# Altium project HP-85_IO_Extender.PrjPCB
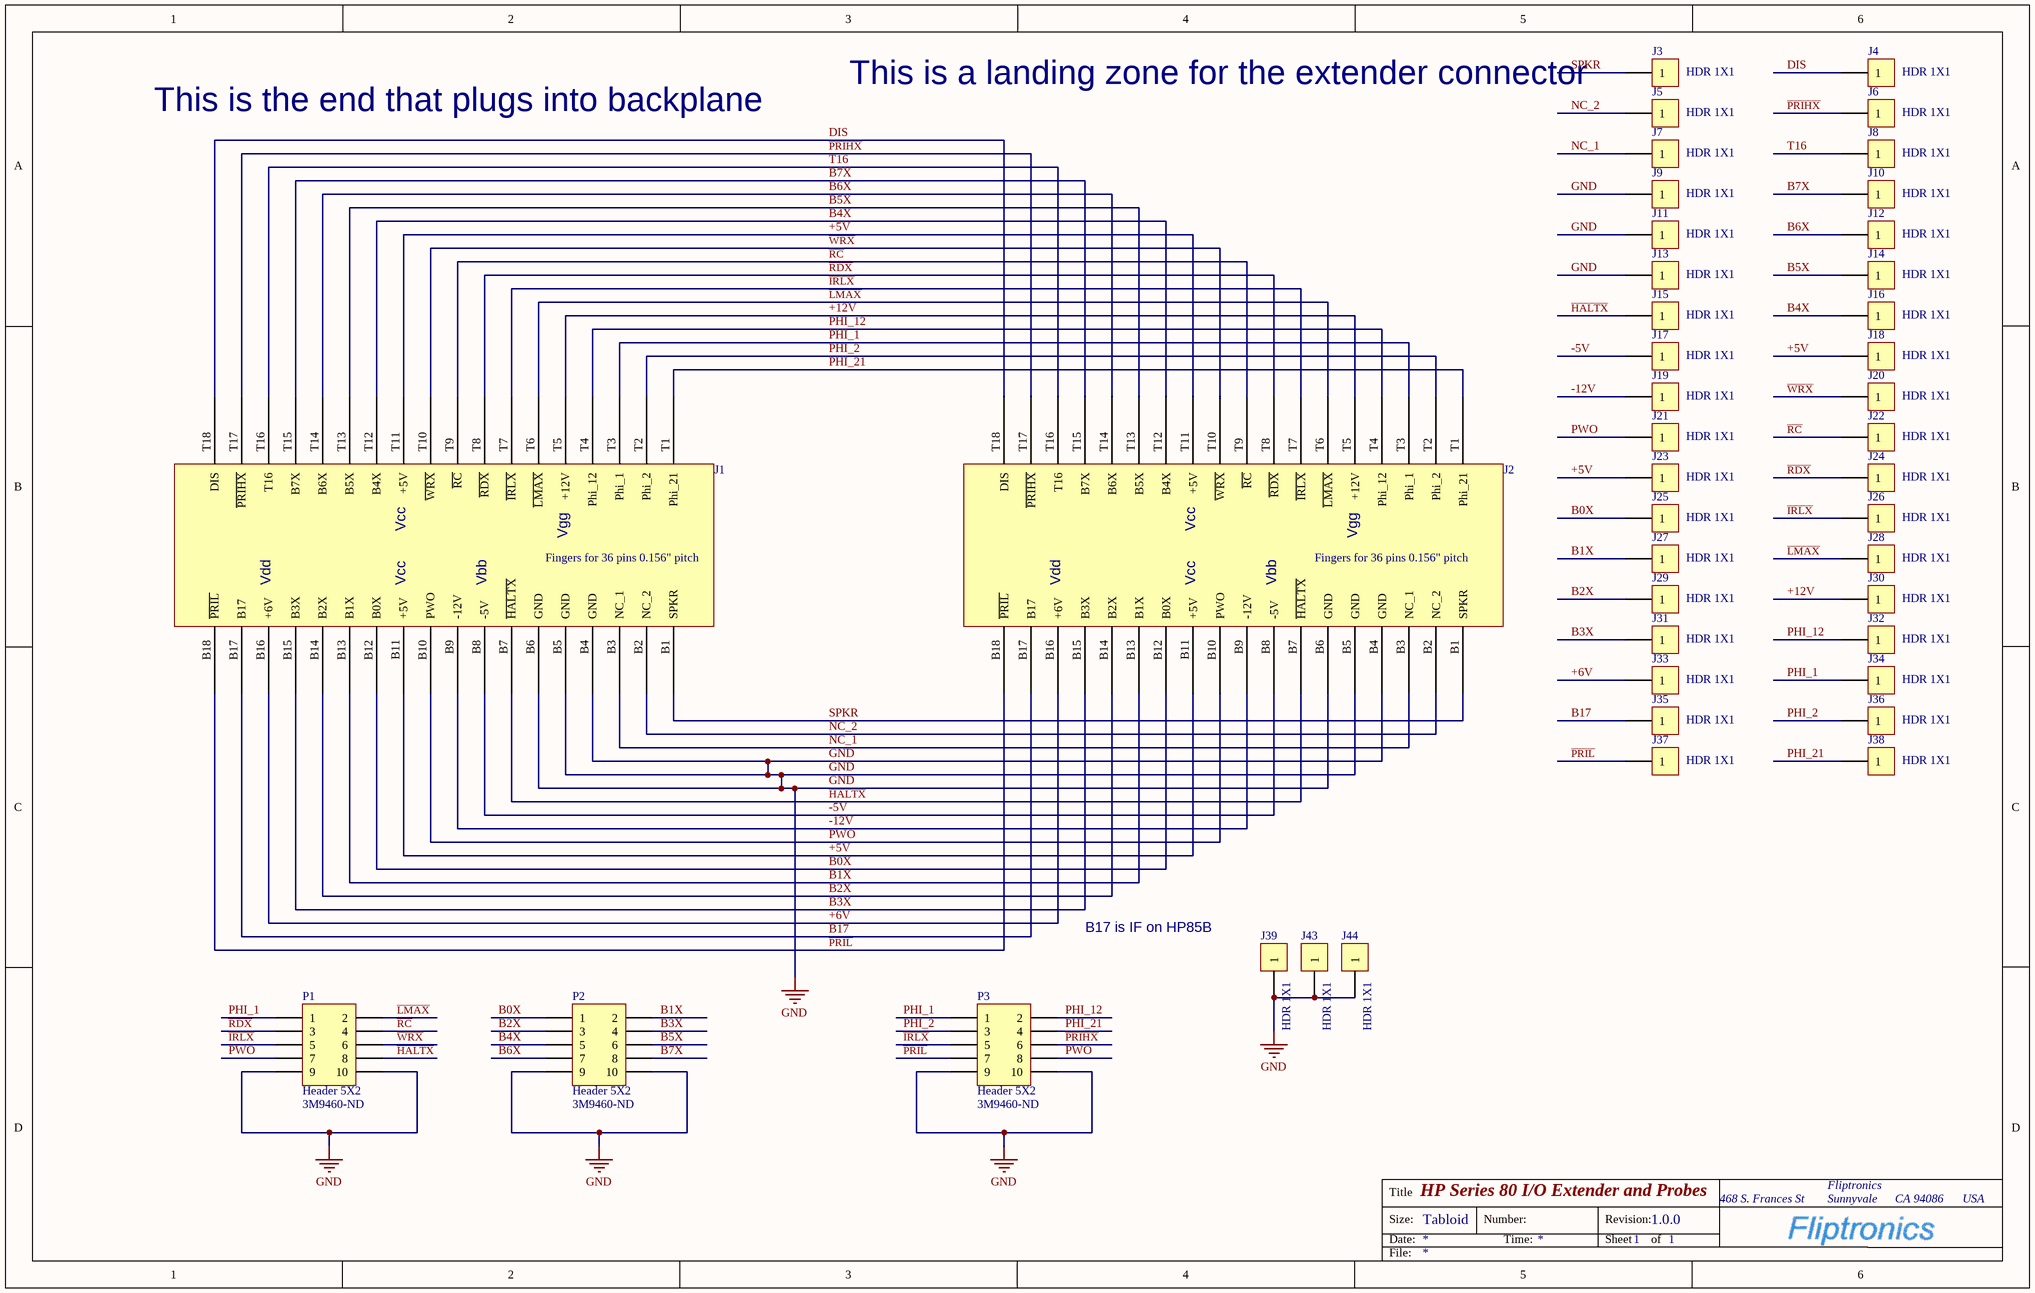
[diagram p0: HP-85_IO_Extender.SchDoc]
1 sheet, 44 parts. Net scope: global (net labels, ports and power ports of the same name join across sheets).
Board file: HP-85_IO_Extender.PcbDoc

## Sheet HP-85_IO_Extender.SchDoc: HP Series 80 I/O Extender and Probes
size B; ApprovedBy: Philip Freidin; CheckedBy: Philip Freidin; Author: Philip Freidin; Organization: Fliptronics; Address1: 468 S. Frances St; Address2: Sunnyvale; Address3: CA 94086; Address4: USA; Revision: 1.0.0; SheetNumber: 1; SheetTotal: 1

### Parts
J1  Fingers for 36 pins 0.156" pitch  [Fingers for 36 pins 0.156" pitch]
J2  Fingers for 36 pins 0.156" pitch  [Fingers for 36 pins 0.156" pitch]
J3  HDR 1X1  [HDR_1X1_2MM54_round]
J4  HDR 1X1  [HDR_1X1_2MM54_round]
J5  HDR 1X1  [HDR_1X1_2MM54_round]
J6  HDR 1X1  [HDR_1X1_2MM54_round]
J7  HDR 1X1  [HDR_1X1_2MM54_round]
J8  HDR 1X1  [HDR_1X1_2MM54_round]
J9  HDR 1X1  [HDR_1X1_2MM54_round]
J10  HDR 1X1  [HDR_1X1_2MM54_round]
J11  HDR 1X1  [HDR_1X1_2MM54_round]
J12  HDR 1X1  [HDR_1X1_2MM54_round]
J13  HDR 1X1  [HDR_1X1_2MM54_round]
J14  HDR 1X1  [HDR_1X1_2MM54_round]
J15  HDR 1X1  [HDR_1X1_2MM54_round]
J16  HDR 1X1  [HDR_1X1_2MM54_round]
J17  HDR 1X1  [HDR_1X1_2MM54_round]
J18  HDR 1X1  [HDR_1X1_2MM54_round]
J19  HDR 1X1  [HDR_1X1_2MM54_round]
J20  HDR 1X1  [HDR_1X1_2MM54_round]
J21  HDR 1X1  [HDR_1X1_2MM54_round]
J22  HDR 1X1  [HDR_1X1_2MM54_round]
J23  HDR 1X1  [HDR_1X1_2MM54_round]
J24  HDR 1X1  [HDR_1X1_2MM54_round]
J25  HDR 1X1  [HDR_1X1_2MM54_round]
J26  HDR 1X1  [HDR_1X1_2MM54_round]
J27  HDR 1X1  [HDR_1X1_2MM54_round]
J28  HDR 1X1  [HDR_1X1_2MM54_round]
J29  HDR 1X1  [HDR_1X1_2MM54_round]
J30  HDR 1X1  [HDR_1X1_2MM54_round]
J31  HDR 1X1  [HDR_1X1_2MM54_round]
J32  HDR 1X1  [HDR_1X1_2MM54_round]
J33  HDR 1X1  [HDR_1X1_2MM54_round]
J34  HDR 1X1  [HDR_1X1_2MM54_round]
J35  HDR 1X1  [HDR_1X1_2MM54_round]
J36  HDR 1X1  [HDR_1X1_2MM54_round]
J37  HDR 1X1  [HDR_1X1_2MM54_round]
J38  HDR 1X1  [HDR_1X1_2MM54_round]
J39  HDR 1X1  [HDR_1X1_2MM54_round]
J43  HDR 1X1  [HDR_1X1_2MM54_round]
J44  HDR 1X1  [HDR_1X1_2MM54_round]
P1  Header 5X2  Supplier Part Number 1: 3M9460-ND  [HDR_5X2 alt 1]
P2  Header 5X2  Supplier Part Number 1: 3M9460-ND  [HDR_5X2 alt 1]
P3  Header 5X2  Supplier Part Number 1: 3M9460-ND  [HDR_5X2 alt 1]

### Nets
GND: J1.B4(GND) J1.B5(GND) J1.B6(GND) J2.B4(GND) J2.B5(GND) J2.B6(GND) J9.1 J11.1 J13.1 J39.1 J43.1 J44.1 P1.9 P1.10 P2.9 P2.10 P3.9 P3.10
+5V: J1.B11(+5V) J1.T11(+5V) J2.B11(+5V) J2.T11(+5V) J18.1 J23.1
+6V: J1.B16(+6V) J2.B16(+6V) J33.1
+12V: J1.T5(+12V) J2.T5(+12V) J30.1
-5V: J1.B8(-5V) J2.B8(-5V) J17.1
-12V: J1.B9(-12V) J2.B9(-12V) J19.1
~{HALTX}: J1.B7(~{HALTX}) J2.B7(~{HALTX}) J15.1 P1.8
~{IRLX}: J1.T7(~{IRLX}) J2.T7(~{IRLX}) J26.1 P1.5 P3.5
~{LMAX}: J1.T6(~{LMAX}) J2.T6(~{LMAX}) J28.1 P1.2
~{PRIHX}: J1.T17(~{PRIHX}) J2.T17(~{PRIHX}) J6.1 P3.6
~{PRIL}: J1.B18(~{PRIL}) J2.B18(~{PRIL}) J37.1 P3.7
~{RC}: J1.T9(~{RC}) J2.T9(~{RC}) J22.1 P1.4
~{RDX}: J1.T8(~{RDX}) J2.T8(~{RDX}) J24.1 P1.3
~{WRX}: J1.T10(~{WRX}) J2.T10(~{WRX}) J20.1 P1.6
B0X: J1.B12(B0X) J2.B12(B0X) J25.1 P2.1
B1X: J1.B13(B1X) J2.B13(B1X) J27.1 P2.2
B2X: J1.B14(B2X) J2.B14(B2X) J29.1 P2.3
B3X: J1.B15(B3X) J2.B15(B3X) J31.1 P2.4
B4X: J1.T12(B4X) J2.T12(B4X) J16.1 P2.5
B5X: J1.T13(B5X) J2.T13(B5X) J14.1 P2.6
B6X: J1.T14(B6X) J2.T14(B6X) J12.1 P2.7
B7X: J1.T15(B7X) J2.T15(B7X) J10.1 P2.8
B17: J1.B17 J2.B17 J35.1
DIS: J1.T18(DIS) J2.T18(DIS) J4.1
NC_1: J1.B3(NC_1) J2.B3(NC_1) J7.1
NC_2: J1.B2(NC_2) J2.B2(NC_2) J5.1
PHI_1: J1.T3(Phi_1) J2.T3(Phi_1) J34.1 P1.1 P3.1
PHI_2: J1.T2(Phi_2) J2.T2(Phi_2) J36.1 P3.3
PHI_12: J1.T4(Phi_12) J2.T4(Phi_12) J32.1 P3.2
PHI_21: J1.T1(Phi_21) J2.T1(Phi_21) J38.1 P3.4
PWO: J1.B10(PWO) J2.B10(PWO) J21.1 P1.7 P3.8
SPKR: J1.B1(SPKR) J2.B1(SPKR) J3.1
T16: J1.T16 J2.T16 J8.1

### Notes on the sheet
- (near J3) This is a landing zone for the extender connector
- This is the end that plugs into backplane
- B17 is IF on HP85B

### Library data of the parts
J1 J2 = J Fingers for 36 pins 0.156" pitch for HP85: Fingers for 36 pins 0.156" pitch for HP85
J3-J39 J43 J44 = J Header 1X1: Header, 1-Pin; 1 MANUFACTURE A: Fliptronics; 1 MANUFACTURE A WEBSITE: ~
P1-P3 = J Header 5X2: Header, 5-Pin, Dual row; 1 MANUFACTURE A WEBSITE: ~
